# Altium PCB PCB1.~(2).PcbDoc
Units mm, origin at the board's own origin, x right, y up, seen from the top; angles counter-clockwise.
Board outline 127 x 101.6 mm, 3 copper layers (Top Layer, Internal Plane 1, Bottom Layer); 15 components, 13 nets, 51 pads, 0 vias.
Unrouted connection lines stored in the file: 1.
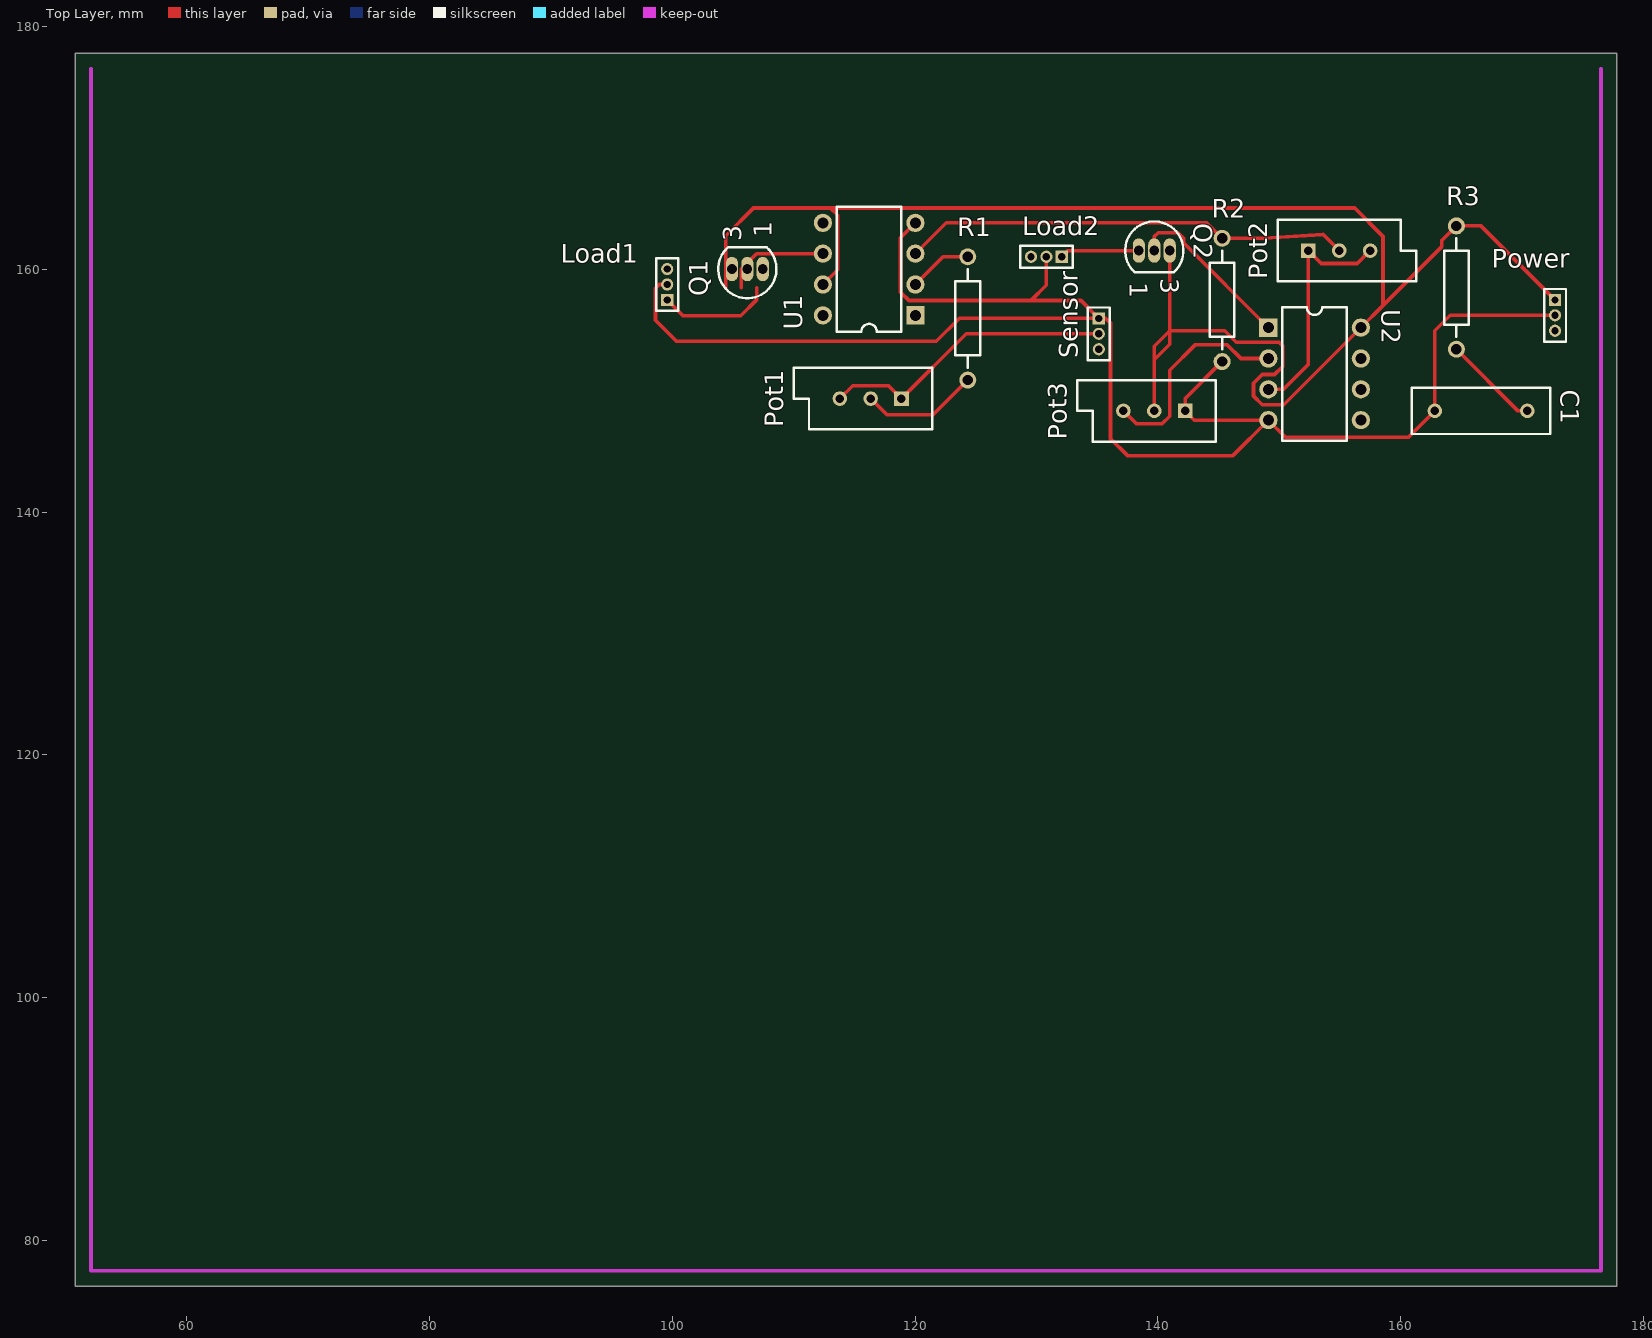
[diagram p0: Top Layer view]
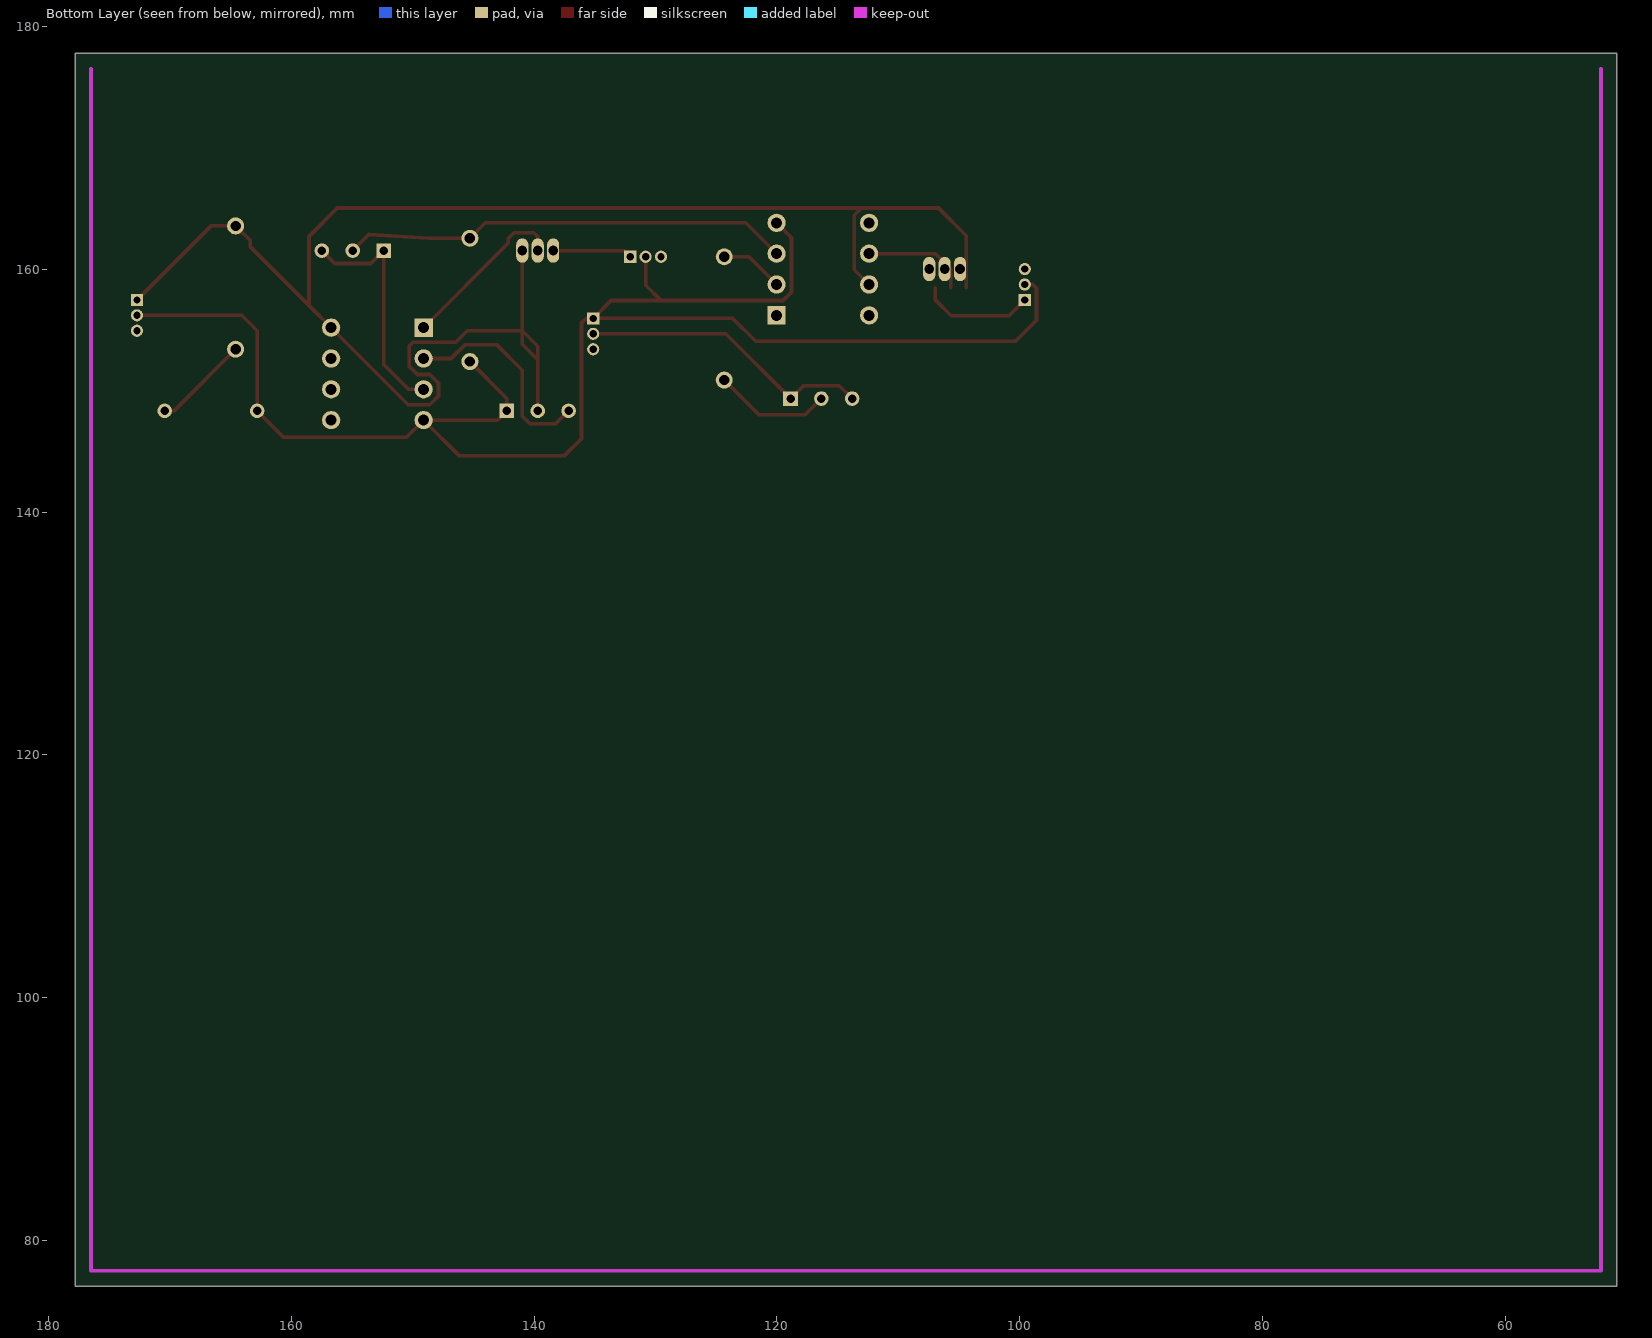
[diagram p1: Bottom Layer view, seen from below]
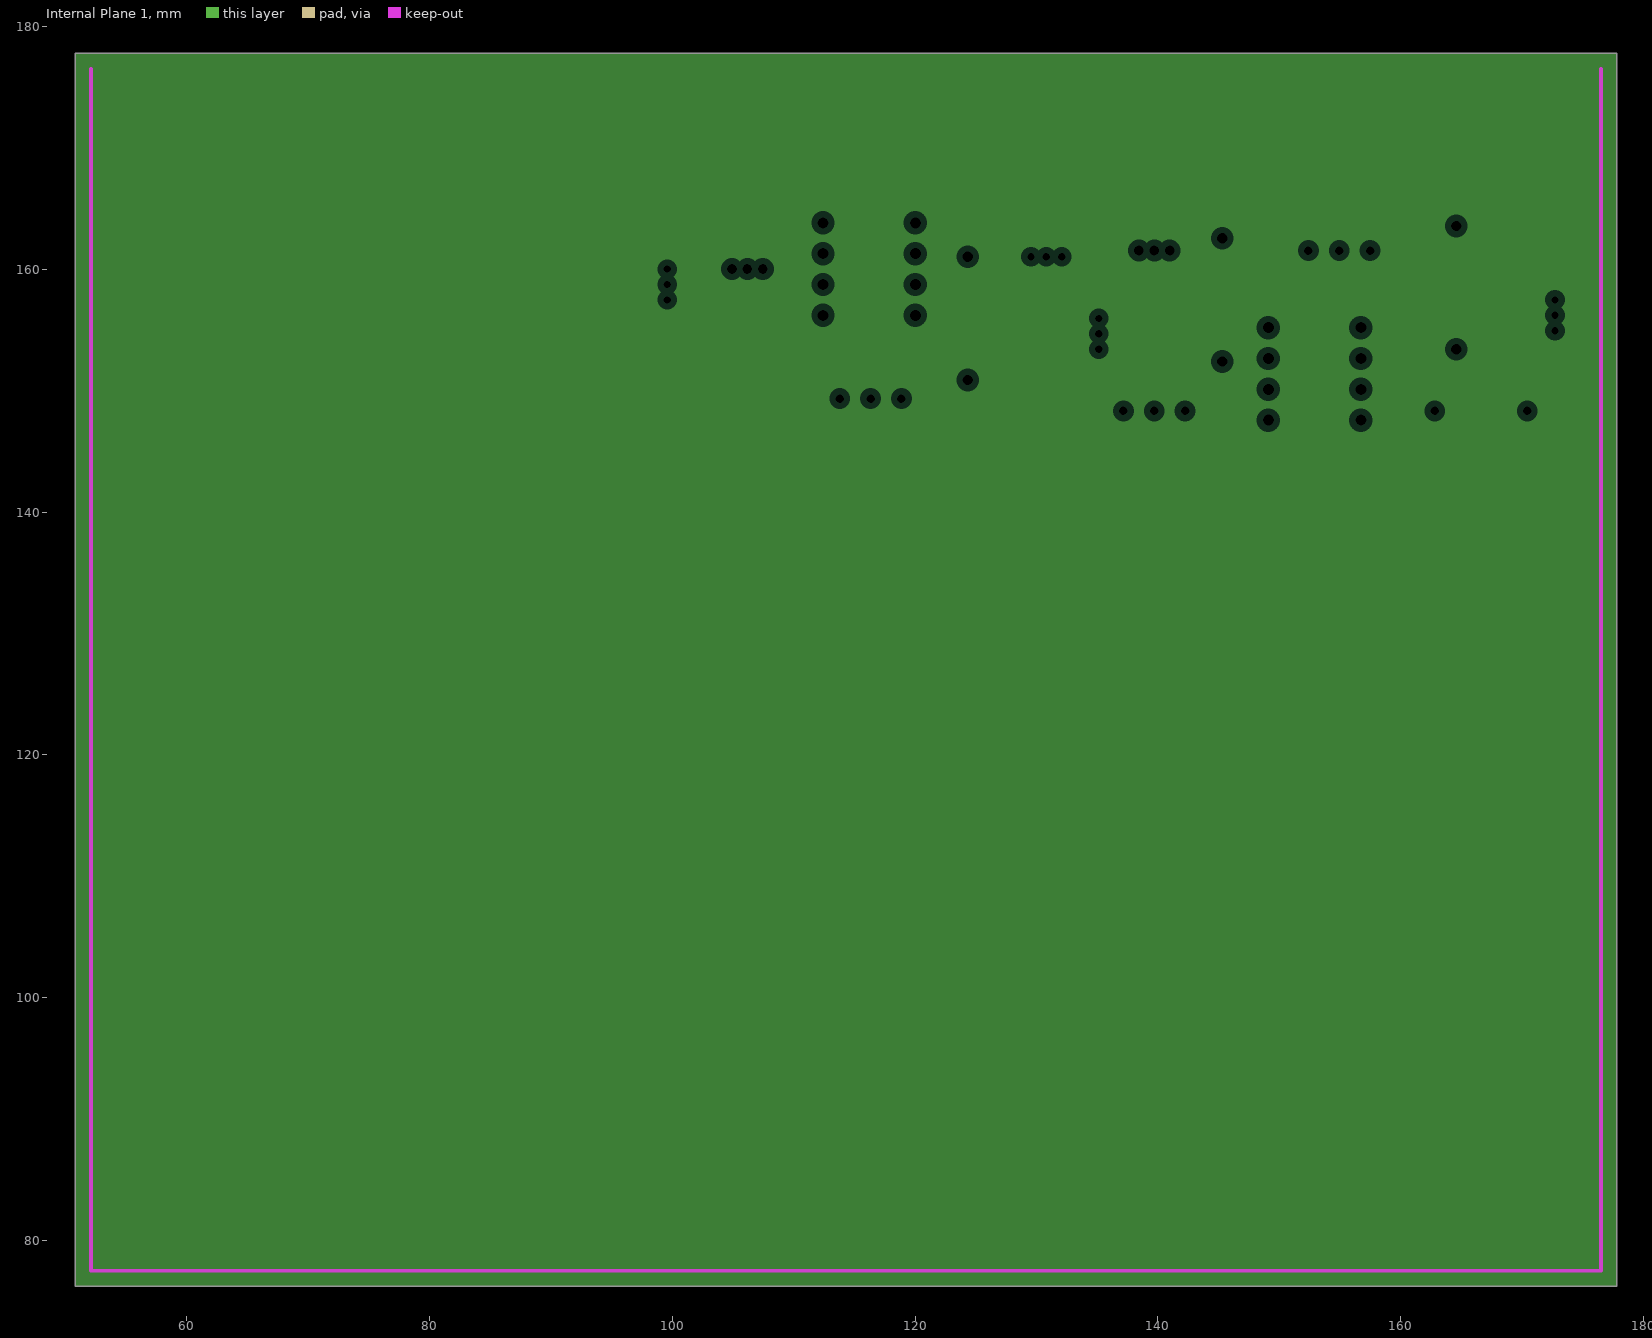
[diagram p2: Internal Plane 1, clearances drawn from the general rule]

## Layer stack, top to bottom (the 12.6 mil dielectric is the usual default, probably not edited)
Top Layer: signal copper 0.0356
Dielectric: dielectric 0.32, FR-4, Dk 4.8
Internal Plane 1: plane copper 0.0356
Dielectric: dielectric 0.32, FR-4, Dk 4.8
Bottom Layer: signal copper 0.0356

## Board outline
50.8,76.2 177.8,76.2 177.8,177.8 50.8,177.8

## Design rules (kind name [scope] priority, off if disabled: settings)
Clearance [All] p1: gap=0.3
ComponentClearance [All] p1: gap=0.254 collisioncheckmode=3 verticalgap=0.254
PlaneClearance [All] p1: clearance=0.508
PlaneConnect [All] p1: planeconnectstyle=Relief reliefexpansion=0.508 reliefentries=4 reliefconductorwidth=0.254 reliefairgap=0.254
PolygonConnect [All] p1: connectstyle=Relief reliefconductorwidth=0.254 reliefentries=4 polygonreliefangle="90 Angle"
RoomDefinition Sheet1 [InComponentClass('Sheet1')] p1: confinementstyle=ConfineIn formatcopy=TRUE lockcomponents=FALSE outline 0,0 50.8,0 50.8,25.4 0,25.4
RoutingVias [All] p1: holewidth=0.8 width=1.6 viastyle="Through Hole" minholewidth=0.711 minwidth=1.27 maxholewidth=0.711 maxwidth=1.27
SolderMaskExpansion [All] p1: expansion=0.102
TestPointUsage [All] p1: valid=0 allowmultiple=FALSE
Testpoint [All] p1: side=15 testpointundercomponent=TRUE minsize=1.016 maxsize=2.54 preferedsize=1.524 minholesize=0 maxholesize=1.016 preferedholesize=0.813 testpointgrid=0.025 style=1023 order=0-112345678
Width [All] p1: maxlimit=0.3 minlimit=0.3 preferedwidth=0.3
16 further rules are at their usual default settings.

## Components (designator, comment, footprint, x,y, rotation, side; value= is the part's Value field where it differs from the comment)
C1 "Cap" RAD-0.3 166.624,148.336 r0 top
Load1 "MHDR1X3" MHDR1X3 99.568,157.48 r90 top
Load2 "MHDR1X3" MHDR1X3 132.08,161.036 r180 top
Pot1 "RPot" VR5 116.332,149.352 r180 top
Pot2 "RPot" VR5 154.94,161.544 r0 top
Pot3 "RPot" VR5 139.7,148.336 r180 top
Power "MHDR1X3" MHDR1X3 172.72,157.48 r270 top
Q1 "BC547A" SOT54 106.172,160.02 r90 top
Q2 "BC547A" SOT54 139.7,161.544 r270 top
R1 "Res2" AXIAL-0.4 124.333,155.956 r90 top
R2 "Res2" AXIAL-0.4 145.288,157.48 r90 top
R3 "Res2" AXIAL-0.4 164.592,158.496 r90 top
Sensor "MHDR1X3" MHDR1X3 135.128,155.956 r270 top
U1 "LM741J/883" N08E 116.205,160.02 r90 top
U2 "LM393P" P008 152.908,151.384 r270 top

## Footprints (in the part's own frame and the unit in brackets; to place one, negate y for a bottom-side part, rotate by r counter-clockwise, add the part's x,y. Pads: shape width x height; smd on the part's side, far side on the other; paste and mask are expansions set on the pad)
AXIAL-0.4 [mm] "Resistor; 2 Leads"
  round 1.4 hole 0.85: 1(-5.08,0) 2(5.08,0)
  silkscreen extent -4.06,-1.02 4.06,1.02
MHDR1X3 [mm] "Connector; Header; 3 Position"
  rect 1x1 hole 0.6: 1(0,0)
  round 1 hole 0.6: 2(1.27,0) 3(2.54,0)
  silkscreen extent -0.9,-0.9 3.44,0.9
N08E [mm] "DIP; 8 Leads; Row Spacing 7.62 mm; Pitch 2.54 mm"
  rect 1.5x1.5 hole 0.9: 1(-3.81,-3.81)
  round 1.5 hole 0.9: 2(-1.27,-3.81) 3(1.27,-3.81) 4(3.81,-3.81) 5(3.81,3.81) 6(1.27,3.81) 7(-1.27,3.81) 8(-3.81,3.81)
  silkscreen extent -5.15,-2.65 5.15,2.65
P008 [mm] "DIP; 8 Leads; Row Spacing 7.62 mm; Pitch 2.54 mm"
  rect 1.5x1.5 hole 0.9: 1(-3.81,-3.81)
  round 1.5 hole 0.9: 2(-1.27,-3.81) 3(1.27,-3.81) 4(3.81,-3.81) 5(3.81,3.81) 6(1.27,3.81) 7(-1.27,3.81) 8(-3.81,3.81)
  silkscreen extent -5.5,-2.65 5.5,2.65
RAD-0.3 [mm] "Capacitor; 2 Leads"
  round 1.2 hole 0.7: 1(-3.81,0) 2(3.81,0)
  silkscreen extent -5.71,-1.91 5.71,1.91
SOT54 [mm] "TO, Flat Index; 3 In-Line, Axial Leads; Body Dia. 4.6mm; Leads 0.48 x 0.45 mm (max)"
  oval 2x1 hole 0.8: 1(0,-1.27) 2(0,0) 3(0,1.27)
  silkscreen extent -2.4,-2.4 1.8,2.4
VR5 [mm] "Potentiometer; 3 Leads"
  rect 1.2x1.2 hole 0.7: 1(-2.54,0)
  round 1.2 hole 0.7: 2(0,0) 3(2.54,0)
  silkscreen extent -5.08,-2.54 6.35,2.54

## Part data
C1: "Capacitor"
Load1 Load2 Power Sensor: "Header, 3-Pin"
Pot1 Pot2 Pot3: "Potentiometer"
Q1 Q2: "NPN General-purpose Transistor"
R1 R2 R3: "Resistor"
U1: "Operational Amplifier"
U2: "Dual Differential Comparator"

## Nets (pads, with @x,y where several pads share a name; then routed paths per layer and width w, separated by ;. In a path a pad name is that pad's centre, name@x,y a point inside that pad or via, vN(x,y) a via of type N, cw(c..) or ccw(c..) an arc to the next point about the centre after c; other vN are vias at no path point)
GND: C1.1 Load1.2 Load2.2 Pot3.1 Power.2 R2.1 Sensor.1 U1.4 U2.4 | length 139.5
  Top Layer w0.3: Load1.2 98.92,158.75 98.603,158.433 98.603,155.804 100.33,154.076 121.742,154.076 123.622,155.956 Sensor.1 ; U1.4 118.796,162.611 118.796,158.115 119.482,157.429 129.54,157.429 ; Load2.2 130.81,158.699 129.54,157.429 ; R2.1 142.24,149.352 Pot3.1 143.002,147.574 U2.4 ; Power.2 164.084,156.21 162.814,154.94 C1.1 160.63,146.152 150.52,146.152 U2.4 ; 129.54,157.429 133.655,157.429 Sensor.1 ; Sensor.1 135.712,155.956 136.093,155.575 136.093,146.05 137.49,144.653 146.177,144.653 U2.4
NetC1_2: C1.2 R3.1 | length 7.9
  Top Layer w0.3: R3.1 169.672,148.336 C1.2
NetLoad1_1: Load1.1 Q1.1 | length 9.5
  Top Layer w0.3: Load1.1 100.863,156.185 105.639,156.185 106.934,157.48 106.934,158.496
NetLoad2_1: Load2.1 Q2.1 | length 6.6
  Top Layer w0.3: Load2.1 132.588,161.544 Q2.1
NetPot1_1: Pot1.1 Pot1.3 Sensor.2 | length 24.4
  Top Layer w0.3: Pot1.3 114.859,150.419 117.805,150.419 Pot1.1 124.206,154.686 Sensor.2
NetPot1_2: Pot1.2 R1.1 | length 9.7
  Top Layer w0.3: Pot1.2 117.653,148.031 121.488,148.031 R1.1
NetPot2_1: Pot2.1 Pot2.3 U2.3 | length 19.5
  Top Layer w0.3: U2.3 150.344,150.114 152.4,152.17 Pot2.1 153.467,160.477 156.413,160.477 Pot2.3
NetPot2_2: Pot2.2 R2.2 U1.3 | length 37.1
  Top Layer w0.3: U1.3 122.555,163.83 144.018,163.83 R2.2 148.692,162.56 153.619,162.865 Pot2.2
NetPot3_3: Pot3.3 U2.2 | length 17.8
  Top Layer w0.3: Pot3.3 138.227,147.269 140.335,147.269 140.97,147.904 140.97,151.689 143.053,153.772 145.72,153.772 146.838,152.654 U2.2
NetQ1_2: Q1.2 U1.6 | length 8.8
  Top Layer w0.3: 105.664,158.496 105.664,160.02 106.934,161.29 U1.6
NetQ2_2: Q2.2 U2.1 | length 14.1
  Top Layer w0.3: Q2.2 139.7,162.7 140.017,163.017 141.656,163.017 142.113,162.56 142.113,162.179 U2.1
NetR1_2: R1.2 U1.2 | length 5.3
  Top Layer w0.3: U1.2 122.301,161.036 R1.2
VCC: Pot3.2 Power.1 Q1.3 Q2.3 R3.2 U1.7 U2.8 | length 139.3
  Top Layer w0.3: 104.394,158.496 104.394,162.763 106.68,165.049 113.03,165.049 ; U1.7 113.614,159.969 113.614,164.465 113.03,165.049 ; Pot3.2 139.7,152.552 ; Q2.3 140.97,154.94 ; Power.1 166.624,163.576 R3.2 163.373,162.357 163.373,161.849 158.547,157.023 ; 113.03,165.049 156.21,165.049 158.547,162.712 158.547,157.023 ; 139.7,152.552 140.97,153.822 140.97,154.94 ; 139.7,152.552 139.7,153.67 140.97,154.94 ; 140.97,154.94 145.517,154.94 146.463,153.994 149.974,153.994 150.298,153.67 150.298,152.025 149.606,151.333 148.59,151.333 147.879,150.622 147.879,149.555 148.59,148.844 150.368,148.844 U2.8 158.547,157.023
pads on no net: Load1.3 Load2.3 Power.3 Sensor.3 U1.1 U1.5 U1.8 U2.5 U2.6 U2.7

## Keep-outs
Keep-Out Layer:
  lines w0.3: 52.1,176.5 52.1,77.5 176.5,77.5 176.5,176.5

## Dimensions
52.1,77.5 to 176.5,77.5 on Mechanical 1
52.1,77.5 to 52.1,176.5 on Mechanical 1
